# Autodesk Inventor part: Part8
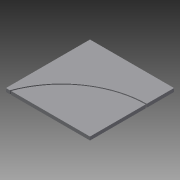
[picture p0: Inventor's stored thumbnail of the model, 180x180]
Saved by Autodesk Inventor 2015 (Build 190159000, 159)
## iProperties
Created: 2015-04
Part Number: Part8
Material: Generic
Document SubType Name: Modeling
Designer: TREINA5
Density: 1 g/cm^3
Appearance: Default
Mass: 129234 g
Surface Area: 48796.1 cm^2
Volume: 129234 cm^3
Author: TREINA5
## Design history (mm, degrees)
sketch "Sketch1"
  geometry: L1 (1500, 4480)-(2980, 4480); L2 (1500, 3000)-(1500, 4480); L3 (1500, 4479.966)-(2980, 4479.966); L4 (1589.964, 2999.966)-(2980, 2999.966); L5 (2980, 4479.966)-(2980, 3999.933); L6 (2980, 3979.966)-(2980, 2999.966); L7 (1500, 3000)-(1568.745, 3000); L8 (1589.977, 3000)-(2980, 3000); A1 r 1490.034 centre (2990, 2489.966) between (2980, 3979.966) and (1589.964, 2999.966); A2 r 1510 centre (2990, 2489.966) between (2980, 3999.933) and (1568.745, 3000); 1 further point
  constraints: 16 end point, 5 point on circle, 2 centre point, 2 point on line
extrude "Extrusion1" new body sketch "Sketch1" distance "d0" = 60; taper "d1" = 0 deg
extrude "Extrusion2" new body sketch "Sketch1" distance "d2" = 60; taper "d3" = 0 deg
body "Solid1"
body "Solid2"
